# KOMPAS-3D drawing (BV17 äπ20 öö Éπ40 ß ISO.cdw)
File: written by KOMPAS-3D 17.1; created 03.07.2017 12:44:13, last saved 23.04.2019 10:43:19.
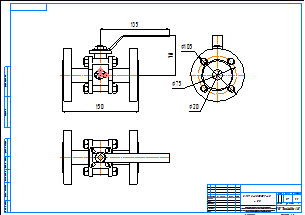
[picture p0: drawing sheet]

Sheet 1: A2, landscape

Title block, sheet 1: name: BV17 Ду20 ФФ Ру40 / с ISO; material: Внимание! Данный продукт является объектом авторского права ООО «Торговый Дом АДЛ». / Запрещается изменение, копирование, распространение / (в том числе путем копирования на другие сайты и ресурсы в Интернете) / или любое иное использование информации и объектов без предварительного / согласия правообладателя (ООО «Торговый Дом АДЛ»).; mass: 1,7; sheets: 1; organisation: ООО "Торговый дом АДЛ"; sheet format: A2; stored path: C:\Users\kka\KOMPAS_Work\!Trash\СС02 СС03 ФФ Смотровые стекла\СС01.cdw

Views: Спереди 1, Проекционный вид 2, Проекционный вид 3
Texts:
  Klimkovich
  ADL
Dimensions and other numbers on the sheet: 150; 135; 78; 75; 105; 20; 1:1; 1; 1,7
